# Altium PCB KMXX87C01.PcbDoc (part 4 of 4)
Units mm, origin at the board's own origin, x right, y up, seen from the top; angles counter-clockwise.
Board outline 109.2 x 85.1 mm, 4 copper layers (Top Layer, Mid-Layer 1, Mid-Layer 2, Bottom Layer); 294 components, 222 nets, 951 pads, 352 vias.
Unrouted connection lines stored in the file: 266.
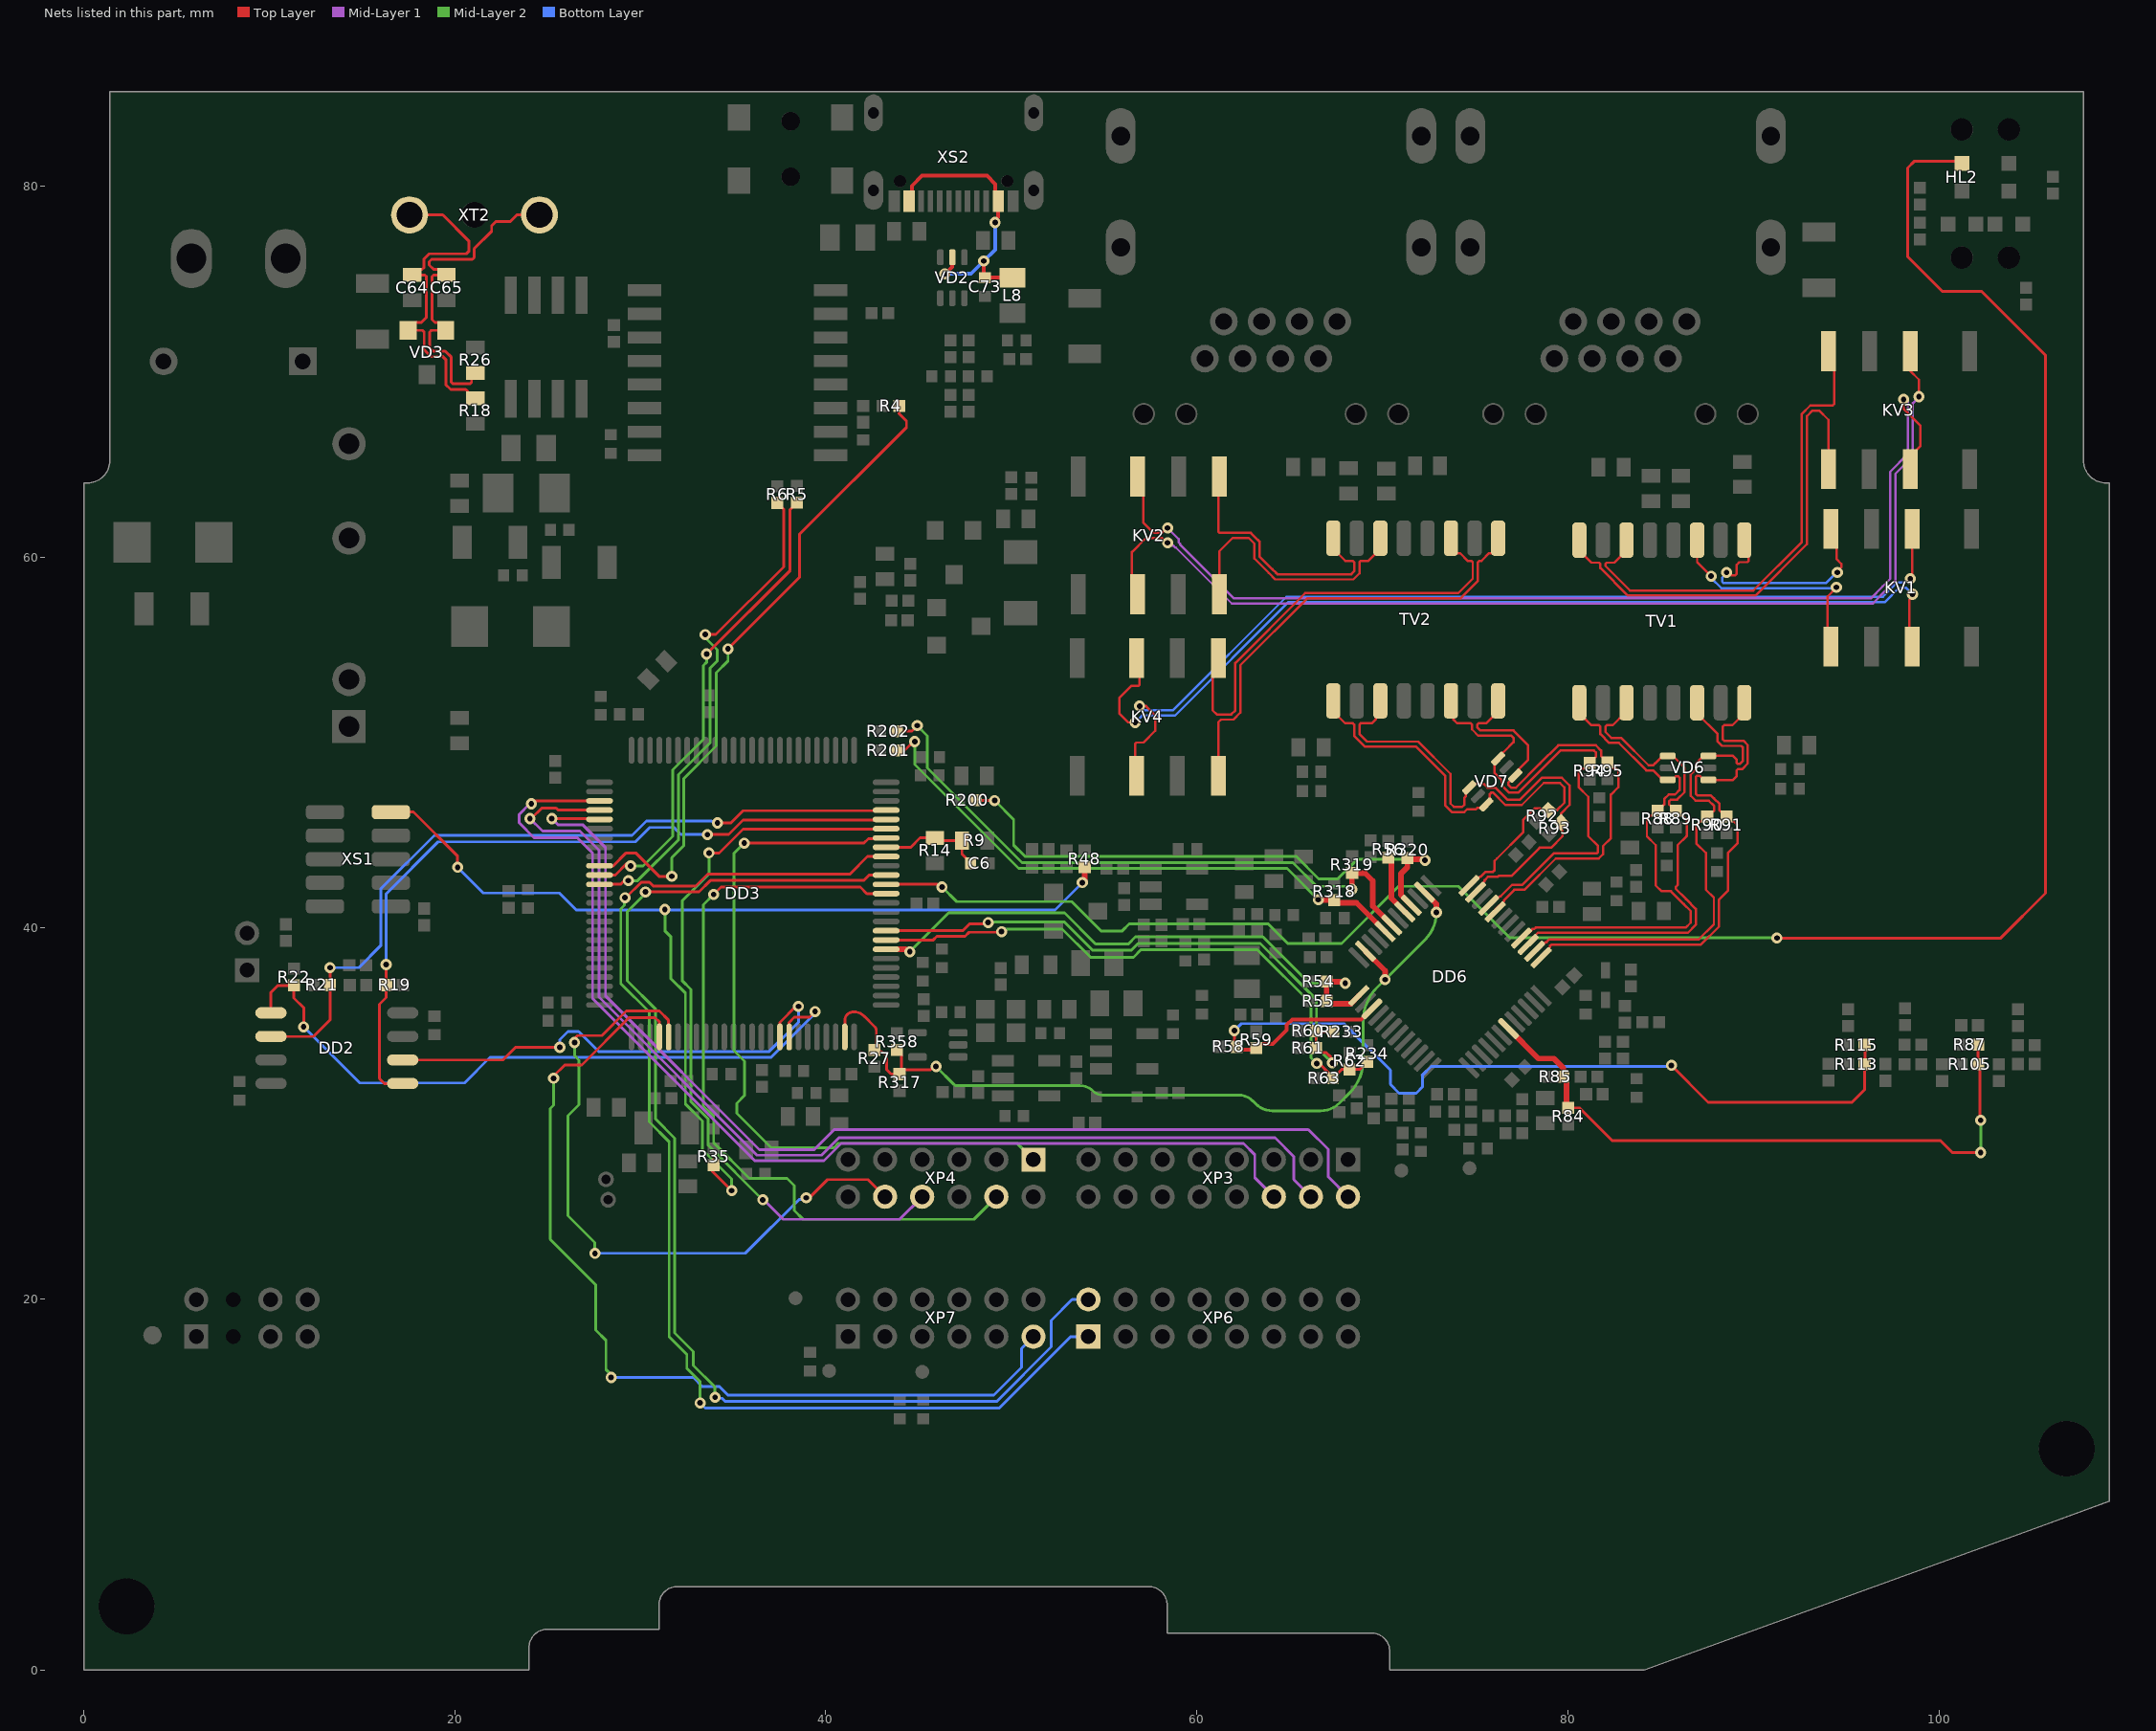
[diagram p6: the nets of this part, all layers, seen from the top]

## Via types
v1: diameter 0.6, hole 0.3, Top Layer to Bottom Layer, tented both sides, 292 vias
v2: diameter 0.6, hole 0.3, Top Layer to Bottom Layer, 60 vias

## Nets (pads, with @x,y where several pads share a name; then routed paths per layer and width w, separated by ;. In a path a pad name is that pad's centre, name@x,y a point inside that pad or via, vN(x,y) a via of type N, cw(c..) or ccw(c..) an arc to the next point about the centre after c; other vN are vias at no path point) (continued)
PE5: DD3.4 XP7.11 | length 50.7
  Top Layer w0.15: v1(25.325,31.9) 25.325,32.018 25.932,32.625 26.841,32.625 29.391,35.175 30.8,35.175 31.025,34.95 DD3.4@31.025,34.132
  Mid-Layer 2 w0.15: v1(25.325,31.9) 25.332,31.893 25.332,30.455 25.15,30.273 25.15,23.219 27.6,20.769 27.6,18.326 28.15,17.776 28.15,16.196 28.277,16.069 28.277,16.047 28.426,15.898 v1(28.426,15.776)
  Bottom Layer w0.15: v1(28.426,15.776) 32.849,15.776 33.35,15.275 34.275,15.275 34.725,14.825 49.06,14.825 50.55,16.315 50.55,17.331 XP7.11@51.195,17.976
PE6: DD3.5 XP4.10 | length 37
  Top Layer w0.15: v1(26.451,33.827) 26.451,34.035 26.5,34.084 26.621,34.204 27.926,34.204 29.246,35.525 31.026,35.525 31.525,35.026 DD3.5@31.525,34.132 ; v1(38.943,25.457) 39.068,25.457 39.087,25.437 40.09,26.44 42.27,26.44 XP4.10@43.195,25.515
  Mid-Layer 2 w0.15: v1(26.451,33.827) 26.451,33.124 26.5,33.075 26.699,32.876 26.699,30.478 26.1,29.879 26.1,24.5 27.55,23.05 27.55,22.467 v1(27.556,22.461)
  Bottom Layer w0.15: v1(27.556,22.461) 27.565,22.47 35.659,22.47 38.564,25.375 38.862,25.375 v1(38.943,25.457)
PE7: DD3.38 XP4.4 | length 41.7
  Top Layer w0.15: v1(33.952,41.811) 34.357,42.215 41.851,42.215 42.209,41.857 DD3.38@43.25,41.857
  Mid-Layer 2 w0.15: v1(33.952,41.811) 33.4,41.258 33.4,30.394 33.952,29.841 33.952,28.423 35.875,26.5 37.913,26.5 38.3,26.113 38.3,24.781 38.78,24.301 47.981,24.301 XP4.4@49.195,25.515
PE9: DD3.40 XP6.2 | length 66.3
  Top Layer w0.15: v1(30.275,41.95) 33.16,41.95 33.775,42.565 42.04,42.565 42.332,42.857 DD3.40@43.25,42.857
  Mid-Layer 2 w0.15: v1(30.275,41.95) 30.275,41.863 29.299,40.887 29.299,37.151 30.827,35.623 30.827,29.696 31.852,28.67 31.852,18.168 32.86,17.16 32.86,16.419 34.027,15.252 v1(34.027,14.7)
  Bottom Layer w0.15: v1(34.027,14.7) 34.073,14.654 34.402,14.654 34.58,14.475 49.205,14.475 52.15,17.42 52.15,18.85 53.276,19.976 XP6.2@54.153,19.976
PE11: DD3.42 XP6.1 | length 66.9
  Top Layer w0.15: v1(29.174,41.64) 29.223,41.64 30.058,42.475 30.492,42.475 30.702,42.265 32.98,42.265 33.63,42.915 41.303,42.915 42.245,43.857 DD3.42@43.25,43.857
  Mid-Layer 2 w0.15: v1(29.174,41.64) 29.174,41.602 29.144,41.572 29.144,41.227 28.949,41.032 28.949,37.006 30.477,35.478 30.477,29.551 31.552,28.475 31.552,17.973 32.51,17.015 32.51,16.26 33.225,15.545 v1(33.225,14.4)
  Bottom Layer w0.15: v1(33.225,14.4) 33.5,14.125 49.35,14.125 53.201,17.976 XP6.1@54.153,17.976
PE13: DD3.44 XP4.1 | length 40.1
  Top Layer w0.15: v1(35.6,44.581) 42.055,44.581 42.292,44.818 42.53,44.818 42.54,44.829 DD3.44@43.209,44.829
  Mid-Layer 2 w0.15: v1(35.6,44.581) 35.05,44.031 35.05,33.39 35.617,32.822 35.617,30.975 35.2,30.558 35.2,30.019 37.061,28.157 40.442,28.157 40.685,28.4 50.311,28.4 XP4.1@51.195,27.515
PE14: DD3.45 XP4.8 | length 40.7
  Top Layer w0.15: v1(33.7,44.05) 34.255,44.05 35.533,45.327 43.22,45.327 DD3.45@43.25,45.357
  Mid-Layer 1 w0.15: v1(36.602,25.351) 36.656,25.351 36.69,25.317 37.706,24.301 43.981,24.301 XP4.8@45.195,25.515
  Mid-Layer 2 w0.15: v1(33.7,44.05) 33.7,42.914 32.254,41.468 32.254,37.166 32.729,36.691 32.729,30.641 33.652,29.717 33.652,28.298 36.6,25.351 v1(36.602,25.351)
PWR_OK: C6.1 DD3.43 R9.1 R14.2 | length 5.8
  Top Layer w0.15: DD3.43@43.25,44.357 44.577,44.357 45.082,44.862 R14.2@45.882,44.862 46.028,44.717 R9.1@47.339,44.717 47.339,43.991 47.806,43.524 C6.1@47.806,43.499
R\E\S\E\T\: R35.2 R48.1 XS1.9 | length 60.1
  Top Layer w0.15: XS1.9@16.55,46.255 17.77,46.255 20.15,43.875 v1(20.15,43.275) ; R35.2@33.95,27.5 33.878,27.428 33.878,26.897 v1(34.925,25.85)
  Top Layer w0.3: v1(53.828,42.452) 53.954,42.579 R48.1@53.954,43.278
  Mid-Layer 2 w0.15: v1(31.325,41.002) 31.325,39.852 31.635,39.542 31.635,37.29 32.429,36.496 32.429,30.517 33.352,29.593 33.352,28.048 34.925,26.475 v1(34.925,25.85)
  Bottom Layer w0.15: v1(20.15,43.275) 21.536,41.889 25.636,41.889 26.55,40.975 31.298,40.975 v1(31.325,41.002) ; v1@31.325,40.975 52.351,40.975 v1(53.828,42.452)
RD1_N: DD6.1 R91.1 TV1.8 VD6.1 | length 28.7
  Top Layer w0.127: DD6.1@78.564,38.404 78.564,38.516 79.044,38.996 79.044,39.041 79.119,39.116 87.178,39.116 88.15,40.087 88.15,41.539 88.624,42.013 88.624,44.046 89.147,44.57 89.147,45.544 88.943,45.748 88.82,45.748 88.297,46.271 88.249,46.271 88.175,46.345 88.175,46.692 87.878,46.989 87.872,46.989 87.714,47.147 87.003,47.147 86.901,47.249 86.901,48.144 86.975,48.219 87.081,48.219 87.102,48.198 87.123,48.198 VD6.1@87.335,47.986 ; VD6.1@87.585,47.986 87.587,47.984 88.899,47.984 89.093,48.178 89.093,48.493 89.167,48.568 89.387,48.568 89.702,48.883 89.702,49.862 89.465,50.099 88.426,50.099 88.352,50.173 88.352,50.862 88.426,50.937 88.867,50.937 89.51,51.58 TV1.8@89.51,52.15
RD1_P: DD6.2 R90.1 TV1.6 VD6.3 | length 28.7
  Top Layer w0.127: DD6.2@78.211,38.757 78.323,38.757 78.803,39.237 78.848,39.237 79.004,39.393 87.064,39.393 87.873,40.202 87.873,41.637 87.447,42.063 87.447,44.046 86.925,44.568 86.925,45.544 87.13,45.748 87.252,45.748 87.775,46.271 87.823,46.271 87.898,46.345 87.898,46.578 87.823,46.652 87.817,46.652 87.599,46.87 86.887,46.87 86.624,47.133 86.624,48.259 86.896,48.531 86.896,48.869 87.202,49.175 87.21,49.175 87.322,49.286 VD6.3@87.585,49.286 88.899,49.286 89.093,49.093 89.093,48.919 89.167,48.845 89.272,48.845 89.425,48.997 89.425,49.747 89.351,49.822 88.312,49.822 88.075,50.058 88.075,50.458 86.97,51.563 TV1.6@86.97,52.15
RD2_N: DD6.8 R95.1 TV2.8 VD7.1 | length 27.6
  Top Layer w0.127: DD6.8@76.089,40.878 76.089,40.991 76.569,41.471 76.569,41.516 77.117,42.063 77.665,42.063 79.351,43.75 81.665,43.75 81.902,43.987 81.902,44.427 82.325,44.85 82.325,47.193 82.727,47.595 82.727,48.463 82.573,48.618 82.45,48.618 R95.1@82.139,48.929 81.877,49.191 81.871,49.191 81.796,49.265 81.796,49.57 81.517,49.849 79.483,49.849 78.494,48.861 77.209,47.576 76.947,47.576 76.789,47.734 76.789,47.839 77.162,48.213 VD7.1@77.162,48.218 77.348,48.404 77.348,48.541 77.395,48.588 77.395,48.602 77.85,49.057 77.85,49.871 77.071,50.65 75.287,50.65 75.112,50.825 75.112,50.962 75.187,51.037 75.6,51.037 76.244,51.68 TV2.8@76.244,52.25
RD2_P: DD6.9 R94.1 TV2.6 VD7.3 | length 27.6
  Top Layer w0.127: TV2.6@73.704,52.25 73.838,52.116 73.838,51.237 74.038,51.037 74.761,51.037 74.835,50.962 74.835,50.71 75.173,50.373 76.956,50.373 77.07,50.259 77.07,50.026 76.884,49.839 76.865,49.822 76.847,49.804 76.243,49.199 VD7.3@76.243,49.137 76.243,49.001 76.051,48.809 76.051,48.356 76.423,47.984 76.423,47.708 76.832,47.299 77.324,47.299 79.598,49.572 81.403,49.572 81.519,49.456 81.519,49.252 R94.1@81.445,49.177 ; DD6.9@75.736,41.232 75.848,41.232 76.328,41.712 76.373,41.712 77.002,42.34 77.55,42.34 79.236,44.027 81.551,44.027 81.625,44.101 81.625,44.425 81.101,44.949 81.101,47.075 80.594,47.582 80.594,48.45 80.749,48.604 80.871,48.604 R94.1@81.183,48.916 R94.1@81.444,49.177
Ref_Clk_Out_Dis: DD6.17 R56.2 | length 3.2
  Top Layer w0.3: R56.2@70.487,43.791 70.487,41.602 DD6.17@71.21,40.878
RMII_CLK: DD3.24 DD6.14 DD6.23 R27.1 R317.2 R358.1 | length 48.1
  Top Layer w0.15: DD3.24@41.025,34.132 41.025,35.037 cw(c41.452,35.037) 41.15,35.338 cw(c41.498,34.991) 41.498,35.483 cw(c41.498,34.666) 42.075,35.243 42.635,34.683 cw(c42.431,34.479) 42.72,34.479 R27.1@42.72,33.562 ; R27.1@42.625,33.425 cw(c42.625,32.613) 43.199,33.187 43.222,33.165 cw(c43.109,33.052) 43.268,33.052 43.268,32.384 43.527,32.125 44.076,32.125 R317.2@44.076,32.352 ; R358.1@43.835,33.428 44.076,33.187 R317.2@44.076,32.352 ; v1(45.938,32.537) 45.851,32.45 45.728,32.45 45.63,32.352 R317.2@44.076,32.352
  Top Layer w0.3: DD6.23@69.089,38.757 70.15,37.696 v2(70.149,37.223) ; DD6.14@72.271,41.939 72.912,41.298 v1(72.912,40.848)
  Mid-Layer 2 w0.15: v1(45.938,32.537) 46.904,31.572 ccw(c47.063,31.731) 47.063,31.506 53.686,31.506 cw(c53.686,30.461) 54.425,31.2 ccw(c54.914,31.689) 54.914,30.997 62.25,30.997 cw(c62.25,29.904) 63.023,30.677 63.179,30.521 ccw(c64.075,31.417) 64.075,30.15 66.674,30.15 ccw(c66.674,31.601) 67.7,30.575 68.231,31.106 ccw(c66.435,32.902) 68.975,32.902 68.975,34.997 cw(c71.515,34.997) 69.719,36.793 v2(70.149,37.223) 72.303,39.376 ccw(c70.831,40.848) v1(72.912,40.848)
RMII_CRS_DV: DD3.32 DD6.25 R54.1 R55.1 | length 31.6
  Top Layer w0.3: DD3.32@43.25,38.857 44.313,38.857 44.445,38.726 v1(44.526,38.726) ; R55.1@66.996,36.073 R55.1@66.996,36.088 ; v1(68,37.025) 67.917,37.108 66.999,37.108 R54.1@66.996,37.112 R55.1@66.996,36.088 ; DD6.25@68.736,36.353 68.295,35.913 67.171,35.913 R55.1@66.996,36.088
  Mid-Layer 2 w0.15: v1(44.526,38.726) 46.614,40.814 47.528,40.814 47.539,40.825 52.865,40.825 54.54,39.15 56.315,39.15 56.69,39.525 63.56,39.525 66.06,37.025 v1(68,37.025)
RMII_RXD0: DD3.33 R62.1 R63.1 R234.2 | length 32
  Top Layer w0.15: DD3.33@43.25,39.357 45.789,39.357 45.982,39.55 47.501,39.55 47.726,39.775 49.442,39.775 v1(49.475,39.808) ; v1(66.463,32.7) 66.549,32.614 66.679,32.614 67.075,32.218 67.075,32.15 R63.1@67.325,31.9 67.802,32.377 R62.1@68.237,32.377 68.776,32.377 R234.2@69.183,32.784
  Mid-Layer 2 w0.15: v1(49.475,39.808) 49.617,39.95 52.75,39.95 54.275,38.425 56.58,38.425 56.98,38.825 63.27,38.825 66.153,35.942 66.153,33.01 v1(66.463,32.7)
RMII_RXD1: DD3.34 R60.1 R61.1 R233.2 | length 32
  Top Layer w0.15: DD3.34@43.25,39.857 43.257,39.864 47.391,39.864 47.752,40.225 48.675,40.225 v1(48.75,40.3) ; R61.1@66.425,33.496 66.425,34.404 R233.2@67.35,34.404 ; R61.1@66.425,33.525 66.672,33.278 66.985,33.278 67.222,33.041
  Mid-Layer 2 w0.15: v1(48.75,40.3) 48.783,40.333 52.862,40.333 54.395,38.8 56.46,38.8 56.835,39.175 63.415,39.175 66.453,36.137 66.453,33.583 v1(67.308,32.728)
RMII_TX_EN: DD6.16 R200.2 R320.1 | length 31.1
  Top Layer w0.15: R200.2@48.083,46.892 48.117,46.857 48.137,46.877 v1(49.102,46.877)
  Top Layer w0.3: R320.1@71.356,43.771 71.356,43.284 70.998,42.925 70.998,41.798 71.175,41.621 DD6.16@71.564,41.232 ; R320.1@71.437,43.708 72.248,43.708 v1(72.3,43.656)
  Mid-Layer 2 w0.15: v1(49.102,46.877) 50.124,45.855 50.124,44.474 50.727,43.871 65.354,43.871 66.575,42.65 67.592,42.65 68.642,43.7 72.256,43.7 v1(72.3,43.656)
RMII_TXD0: DD6.20 R201.2 R318.1 | length 31.5
  Top Layer w0.15: R201.2@43.82,49.582 44.26,49.582 44.731,50.054 v1(44.793,50.054)
  Top Layer w0.3: v1(66.548,41.527) 66.559,41.516 67.404,41.516 R318.1@67.415,41.505 67.562,41.357 68.61,41.357 69.761,40.207 DD6.20@70.15,39.818
  Mid-Layer 2 w0.15: v1(44.793,50.054) 44.793,48.816 50.394,43.214 64.861,43.214 v1(66.548,41.527)
RMII_TXD1: DD6.19 R202.2 R319.1 | length 34.3
  Top Layer w0.15: R202.2@43.829,50.6 43.858,50.629 44.641,50.629 v1(44.927,50.915)
  Top Layer w0.3: v1(68.357,42.083) 68.357,42.95 R319.1@68.372,42.966 69.068,42.966 69.487,42.547 69.487,41.188 DD6.19@70.503,40.171
  Mid-Layer 2 w0.15: v1(44.927,50.915) 45.475,50.367 45.475,48.628 50.582,43.521 65.179,43.521 66.45,42.25 68.068,42.25 68.235,42.083 v1(68.357,42.083)
RS485_N: C64.2 R18.1 VD3.2 XT2.3 | length 18.9
  Top Layer w0.15: XT2.3@17.56,78.451 19.349,78.451 20.75,77.05 20.75,76.477 20.622,76.348 18.623,76.348 18.324,76.049 18.324,75.595 18.236,75.507 18.123,75.507 C64.2@17.823,75.207 ; C64.2@17.698,75.207 C64.2@17.823,75.207 ; R18.1@21.1,68.566 20.975,68.566 20.675,68.866 20.675,68.951 20.587,69.039 19.776,69.039 19.512,69.302 19.512,70.65 19.354,70.809 18.714,70.809 18.348,71.175 18.348,72.133 18.26,72.221 VD3.2@17.482,72.221 17.482,72.272 17.864,72.654 18.197,72.654 18.473,72.93 18.473,75.12 18.385,75.207 C64.2@17.823,75.207
RS485_P: C65.2 R26.1 VD3.1 XT2.1 | length 18.9
  Top Layer w0.15: C65.2@19.548,75.207 C65.2@19.218,75.207 ; R26.1@21.106,69.939 20.9,69.733 20.9,69.426 20.812,69.339 19.9,69.339 19.812,69.426 19.812,70.774 19.478,71.109 18.838,71.109 18.648,71.299 18.648,72.133 18.736,72.221 VD3.1@19.514,72.221 19.514,72.272 19.132,72.654 18.921,72.654 18.773,72.802 18.773,75.12 18.861,75.207 C65.2@19.218,75.207 ; XT2.1@24.56,78.451 23.35,78.451 22.999,78.1 22.225,78.1 21.984,77.859 21.984,77.565 21.05,76.631 21.05,76.149 20.949,76.048 18.747,76.048 18.624,75.925 18.624,75.744 18.861,75.507 19.123,75.507 19.218,75.413 C65.2@19.218,75.207
RS485_RTS: DD3.85 R4.1 | length 35.5
  Top Layer w0.15: DD3.85@27.8,43.357 28.542,43.357 29.237,44.052 29.748,44.052 31.01,42.79 v1(31.695,42.79) ; v1(34.727,55.053) 38.574,58.9 38.574,61.218 44.345,66.989 44.345,67.341 43.95,67.737 R4.1@43.95,68.156
  Mid-Layer 2 w0.15: v1(31.695,42.79) 31.695,43.795 32.35,44.45 32.35,48.075 34.1,49.825 34.1,53.775 34.727,54.402 v1(34.727,55.053)
RS485_RX: DD3.87 R6.1 | length 26.8
  Top Layer w0.15: DD3.87@27.8,42.357 28.929,42.357 29.177,42.606 29.227,42.556 v1(29.352,42.556) ; v1(33.5,55.825) 34.075,55.825 37.725,59.475 37.725,62.575 R6.1@37.375,62.925
  Mid-Layer 2 w0.15: v1(29.352,42.556) 29.851,42.556 32.05,44.755 32.05,48.275 33.75,49.975 33.75,54.005 34.145,54.4 34.145,55.013 33.5,55.658 v1(33.5,55.825)
RS485_TX: DD3.86 R5.1 | length 25.7
  Top Layer w0.15: DD3.86@27.8,42.857 28.65,42.857 29.263,43.47 29.386,43.347 v1(29.475,43.347) ; v1(33.57,54.775) 38.075,59.28 38.075,62.569 R5.1@38.441,62.935
  Mid-Layer 2 w0.15: v1(29.475,43.347) 30.147,43.347 31.75,44.95 31.75,48.525 33.4,50.175 33.4,54.15 33.57,54.32 v1(33.57,54.775)
RX_N: KV1.2 KV4.2 | length 52.8
  Top Layer w0.127: KV4.2@56.757,48.204 56.675,48.286 56.675,49.929 56.749,50.003 57.124,50.003 57.758,50.638 57.758,51.473 57.262,51.969 v2(56.913,51.969) ; v2(98.46,58.836) 98.412,58.836 98.329,58.753 98.575,58.753 KV1.2@98.575,61.524
  Bottom Layer w0.127: v2(56.913,51.969) 56.955,51.969 57.191,51.732 58.701,51.732 64.826,57.857 96.985,57.857 97.759,58.631 98.151,58.631 98.356,58.836 v2(98.46,58.836)
RX_P: KV1.7 KV4.7 | length 52.8
  Top Layer w0.127: v2(56.675,51.087) 56.303,51.087 55.83,51.559 55.83,52.417 56.465,53.052 56.839,53.052 56.913,53.126 56.913,54.398 KV4.7@56.757,54.554 ; KV1.7@98.575,55.174 98.4,55.349 98.4,57.697 98.575,57.872 v2(98.575,58)
  Bottom Layer w0.127: v2(56.675,51.087) 57.044,51.455 58.816,51.455 64.941,57.58 97.099,57.58 97.869,58.35 98.225,58.35 v2(98.575,58)
Speed_Conf_P1: DD6.43 R84.2 R85.1 R87.1 R105.1 | length 35.1
  Top Layer w0.15: R84.2@80.025,30.308 80.623,30.308 82.38,28.55 100.078,28.55 100.728,27.9 v1@102.225,27.9 ; R87.1@102.112,33.711 R105.1@102.112,32.661 102.225,32.547 v1@102.225,29.643
  Top Layer w0.3: DD6.43@76.797,34.585 78.413,32.968 79.247,32.968 79.764,32.452 R85.1@79.764,31.982 79.935,31.812 79.935,30.44 R84.2@80.025,30.35
  Mid-Layer 2 w0.15: v1(102.258,27.9) v1(102.258,29.643)
Speed_Conf_P2: DD6.27 R58.2 R59.1 R113.1 R115.1 | length 50.2
  Top Layer w0.15: v1(62.025,34.475) 62.025,33.621 62.153,33.493 62.153,33.597 R58.2@62.15,33.6 ; v1(85.582,32.599) 87.572,30.61 95.317,30.61 95.997,31.291 R113.1@95.997,32.656 ; R113.1@96.022,32.656 R115.1@96.022,33.675
  Top Layer w0.2: R58.2@62.153,33.493 62.195,33.451 63.2,33.451 63.2,33.521 63.425,33.746 64.09,33.746 64.842,34.497 64.842,34.776 65.14,35.075 68.872,35.075 DD6.27@69.443,35.646
  Bottom Layer w0.15: v1(62.025,34.475) 62.4,34.85 67.925,34.85 70.431,32.344 70.431,31.576 70.907,31.1 71.825,31.1 72.175,31.45 72.175,32.087 72.625,32.538 85.521,32.538 v1(85.582,32.599)
SPI2_CS: DD2.1 DD3.46 R19.1 | length 40.4
  Top Layer w0.15: v1(16.296,38.032) 16.296,36.929 R19.1@16.3,36.925 16.3,36.25 15.94,35.89 15.94,31.885 16.206,31.619 DD2.1@17.19,31.619 ; v1(33.615,45.041) 33.623,45.05 34.76,45.05 35.538,45.828 42.539,45.828 42.54,45.829 43.221,45.829 DD3.46@43.25,45.857
  Bottom Layer w0.15: v1(16.296,38.032) 16.296,38.05 16.305,38.059 16.305,41.855 19.1,44.65 29.732,44.65 30.504,45.422 31.808,45.422 32.189,45.041 v1(33.615,45.041)
SPI2_MISO: DD2.2 DD3.17 | length 26.3
  Top Layer w0.15: DD2.2@17.19,32.889 22.589,32.889 23.275,33.575 v1(25.661,33.575) ; DD3.17@37.525,34.132 37.525,34.915 38.393,35.783 38.401,35.775 v1(38.525,35.775)
  Bottom Layer w0.15: v1(25.661,33.575) 25.661,33.986 26.1,34.425 26.674,34.425 27.749,33.35 36.949,33.35 38.525,34.926 v1(38.525,35.775)
SPI2_MOSI: DD2.5 DD3.18 R22.1 | length 37.9
  Top Layer w0.15: DD2.5@10.09,35.429 10.09,36.537 10.46,36.907 R22.1@11.325,36.907 11.325,36.232 11.85,35.707 v1(11.85,34.675) ; DD3.18@38.025,34.132 38.025,34.92 38.305,35.2 39.123,35.2 v1(39.425,35.502)
  Bottom Layer w0.15: v1(11.85,34.675) 14.875,31.65 20.525,31.65 21.9,33.025 37.048,33.025 39.425,35.402 v1(39.425,35.502)
SPI2_SCK: DD2.6 DD3.47 R21.1 | length 42.2
  Top Layer w0.15: DD2.6@10.09,34.159 10.098,34.15 12.375,34.15 13.275,35.05 R21.1@13.275,36.925 v1(13.275,37.865) ; v1(34.157,45.667) 34.882,45.667 35.544,46.329 DD3.47@43.673,46.329
  Bottom Layer w0.15: v1(13.275,37.865) 14.821,37.865 16.005,39.049 16.005,42.105 18.9,45 29.55,45 30.322,45.772 33.845,45.772 33.863,45.753 34.071,45.753 v1(34.157,45.667)
SPI3_MISO: DD3.79 XP3.4 | length 60.7
  Top Layer w0.15: v1(24.05,45.9) 24.115,45.9 24.69,46.475 25.463,46.475 25.563,46.375 27.782,46.375 DD3.79@27.8,46.357
  Mid-Layer 1 w0.15: v1(24.05,45.9) 24.725,45.225 26.745,45.225 27.775,44.195 27.775,36.274 36.292,27.757 39.775,27.757 40.708,28.691 64.215,28.691 65.225,27.681 65.225,26.444 XP3.4@66.153,25.515
SPI3_MOSI: DD3.80 XP3.2 | length 60.4
  Top Layer w0.15: v1(25.225,45.9) 27.757,45.9 DD3.80@27.782,45.875
  Mid-Layer 1 w0.15: v1(25.225,45.9) 25.55,45.575 26.89,45.575 28.125,44.34 28.125,36.349 36.416,28.057 39.367,28.057 40.45,29.141 60.937,29.141 61.413,29.14 66.01,29.141 67.078,28.073 67.078,26.591 XP3.2@68.153,25.515
SPI3_SCK: DD3.78 XP3.6 | length 60.2
  Top Layer w0.15: v1(24.125,46.7) 24.282,46.857 DD3.78@27.8,46.857
  Mid-Layer 1 w0.15: v1(24.125,46.7) 24.037,46.7 23.475,46.138 23.475,45.662 24.262,44.875 26.6,44.875 27.425,44.05 27.425,36.2 36.168,27.457 39.899,27.457 40.833,28.391 62.515,28.391 63.125,27.781 63.125,26.544 XP3.6@64.153,25.515
"System Fault": DD3.39 HL2.A | length 114.1
  Top Layer w0.15: DD3.39@43.25,42.357 45.999,42.357 46.141,42.215 v1(46.263,42.215) ; v1(91.271,39.463) 103.341,39.463 105.75,41.872 105.75,70.883 102.318,74.315 100.202,74.315 98.324,76.193 98.324,80.981 98.693,81.35 101.115,81.35 HL2.A@101.239,81.226
  Mid-Layer 2 w0.15: v1(46.263,42.215) 47.053,41.425 53.255,41.425 54.83,39.85 55.979,39.85 56.354,40.225 63.85,40.225 64.9,39.175 67.8,39.175 70.875,42.25 74.1,42.25 76.875,39.475 91.225,39.475 v1@91.25,39.45
TD1_N: DD6.3 R89.1 TV1.3 VD6.4 | length 27
  Top Layer w0.127: DD6.3@77.972,39.338 78.384,39.75 79.412,39.75 80.215,39.75 86.473,39.75 86.901,40.178 86.901,41.035 86.372,41.564 85.821,42.115 85.821,42.22 85.919,42.319 85.919,44.47 86.399,44.95 86.408,44.958 86.408,45.862 86.204,46.067 86.081,46.067 R89.1@85.82,46.328 85.558,46.59 85.548,46.59 85.474,46.664 85.474,46.844 85.556,46.926 85.893,46.926 86.297,47.33 86.297,48.645 85.753,49.19 VD6.4@85.481,49.19 ; TV1.3@83.16,52.15 83.16,51.649 82.809,51.298 82.779,51.298 82.418,50.937 82.103,50.937 82.029,50.862 82.029,50.574 82.344,50.259 82.866,50.259 84.35,48.775 84.602,48.775 84.696,48.869 85.002,49.175 85.01,49.175 85.122,49.286 VD6.4@85.385,49.286
TD1_P: DD6.4 R88.1 TV1.1 VD6.6 | length 27
  Top Layer w0.127: DD6.4@77.504,39.464 77.616,39.464 78.096,39.944 78.187,39.944 78.269,40.027 79.298,40.027 80.215,40.027 86.358,40.027 86.624,40.292 86.624,40.92 86.257,41.287 85.56,41.984 85.054,41.984 84.742,42.296 84.742,44.47 84.262,44.95 ; TV1.1@80.62,52.15 80.62,51.58 81.264,50.937 81.677,50.937 81.752,50.862 81.752,50.46 82.229,49.982 82.751,49.982 84.236,48.498 84.602,48.498 84.902,48.198 85.002,48.098 85.01,48.098 85.122,47.986 VD6.6@85.385,47.986 ; 84.262,45.025 84.262,45.864 84.467,46.068 84.589,46.068 R88.1@84.851,46.33 85.112,46.591 85.123,46.591 85.197,46.666 85.197,46.958 85.442,47.203 85.778,47.203 86.02,47.445 86.02,48.105 85.946,48.179 85.82,48.179 VD6.6@85.627,47.986
TD2_N: DD6.11 R93.1 TV2.3 VD7.4 | length 27.4
  Top Layer w0.127: TV2.3@69.894,52.25 69.655,52.012 69.655,51.268 69.424,51.037 68.837,51.037 68.762,50.962 68.762,50.475 69.183,50.054 71.938,50.054 73.677,48.315 73.677,46.715 73.86,46.531 74.306,46.531 74.412,46.637 74.412,47.007 74.511,47.106 74.511,47.405 VD7.4@74.688,47.582 74.874,47.768 75.031,47.768 75.037,47.774 75.469,47.774 75.484,47.759 75.668,47.575 76.093,47.575 76.752,46.916 77.404,46.916 78.59,48.102 79.684,48.102 80.09,47.697 80.09,46.637 79.622,46.169 79.622,46.064 79.623,46.062 R93.1@79.623,45.693 79.623,45.323 79.71,45.236 79.71,44.947 79.096,44.333 78.483,44.333 76.962,42.812 76.271,42.812 76.216,42.756 75.688,42.756 75.509,42.577 75.509,42.531 75.029,42.051 75.029,42 DD6.11@75.029,41.939
TD2_P: DD6.12 R92.1 TV2.1 VD7.6 | length 26.4
  Top Layer w0.127: TV2.1@67.354,52.25 67.354,51.68 67.997,51.037 68.411,51.037 68.485,50.962 68.485,50.36 69.069,49.777 71.823,49.777 73.4,48.2 73.4,46.6 73.746,46.254 74.421,46.254 74.571,46.404 75.049,46.404 75.131,46.486 VD7.6@75.43,46.486 ; DD6.12@74.675,42.293 74.787,42.293 75.267,42.773 75.313,42.773 75.574,43.033 75.963,43.033 76.038,43.108 76.038,43.608 76.176,43.747 76.176,43.75 77.587,45.161 77.587,45.833 78.201,46.447 78.49,46.447 78.577,46.36 R92.1@78.947,46.36 79.421,46.36 79.813,46.752 79.813,47.582 79.569,47.825 78.705,47.825 77.519,46.639 76.638,46.639 75.978,47.298 75.873,47.298 75.793,47.218 75.793,46.849 VD7.6@75.607,46.663
TV1_RX_N: KV1.4 TV1.9 | length 12.8
  Top Layer w0.127: v2(88.559,59.175) 88.687,59.175 88.837,59.025 89.026,59.025 89.1,59.099 89.1,59.58 89.247,59.727 89.676,59.727 89.75,59.802 89.75,59.954 89.749,59.956 89.749,60.677 TV1.9@89.51,60.915 ; KV1.4@94.175,61.524 94.48,61.219 94.48,59.9 94.75,59.63 94.75,59.465 94.532,59.247 v2(94.532,59.169)
  Bottom Layer w0.127: v2(88.559,59.175) 88.559,59.13 88.324,58.895 88.324,58.674 88.399,58.6 93.913,58.6 94.482,59.169 v2(94.532,59.169)
TV1_RX_P: KV1.5 TV1.11 | length 12.8
  Top Layer w0.127: TV1.11@86.97,60.915 86.97,59.73 v2@87.725,58.975 ; KV1.5@94.175,55.174 94,55.349 94,57.873 94.48,58.353 v2(94.48,58.371)
  Bottom Layer w0.127: v2(87.725,58.975) 87.725,58.882 88.284,58.323 94.432,58.323 v2(94.48,58.371)
TV1_TX_N: KV3.4 TV1.14 | length 26.2
  Top Layer w0.127: TV1.14@83.16,60.915 83.16,60.345 82.517,59.702 82.103,59.702 82.029,59.627 82.029,59.522 83.349,58.202 89.999,58.202 92.614,60.817 92.614,67.717 93.072,68.175 94.276,68.175 94.35,68.249 94.35,70.8 KV3.4@94.05,71.1
TV1_TX_P: KV3.5 TV1.16 | length 26.2
  Top Layer w0.127: TV1.16@80.62,60.915 80.62,60.345 81.264,59.702 81.677,59.702 81.752,59.627 81.752,59.407 83.234,57.925 90.114,57.925 92.891,60.702 92.891,67.602 93.186,67.898 93.552,67.898 94.05,67.4 KV3.5@94.05,64.75
TV2_RX_N: KV4.4 TV2.9 | length 24.5
  Top Layer w0.127: KV4.4@61.157,48.204 61.157,51.098 61.3,51.24 61.972,51.24 62.352,51.62 62.352,54.177 65.95,57.775 74.204,57.775 75.151,58.721 75.151,59.727 75.225,59.802 75.352,59.802 75.757,60.207 75.937,60.207 76.244,60.514 TV2.9@76.244,61.015
TV2_RX_P: KV4.5 TV2.11 | length 24.5
  Top Layer w0.127: KV4.5@61.157,54.554 60.85,54.246 60.85,51.745 61.078,51.517 61.857,51.517 62.075,51.735 62.075,54.292 65.835,58.052 74.089,58.052 74.874,58.836 74.874,59.727 74.799,59.802 74.596,59.802 74.191,60.207 74.011,60.207 73.704,60.514 TV2.11@73.704,61.015
TV2_TX_N: KV2.4 TV2.14 | length 14.3
  Top Layer w0.127: KV2.4@61.217,57.995 61.217,60.317 61.932,61.032 62.793,61.032 63.1,60.725 63.1,59.925 63.875,59.15 64.227,58.798 68.438,58.798 68.762,59.122 68.762,59.727 68.837,59.802 69.25,59.802 69.894,60.445 TV2.14@69.894,61.015
TV2_TX_P: KV2.5 TV2.16 | length 14.3
  Top Layer w0.127: KV2.5@61.217,64.345 61.157,64.285 61.157,61.383 61.232,61.309 62.908,61.309 63.296,60.921 63.377,60.84 63.377,60.04 64.071,59.346 64.267,59.15 64.342,59.075 68.323,59.075 68.485,59.237 68.485,59.727 68.411,59.802 67.997,59.802 67.354,60.445 TV2.16@67.354,61.015
TX_N: KV2.2 KV3.2 | length 59.4
  Top Layer w0.127: KV2.2@56.817,57.995 56.5,58.313 56.5,60.275 57.257,61.032 57.734,61.032 58.114,61.032 58.376,60.77 v2(58.425,60.77) ; KV3.2@98.45,71.1 98.163,70.813 98.693,70.284 98.45,70.04 98.925,69.565 v2(98.925,68.65)
  Mid-Layer 1 w0.127: v2(58.425,60.77) 58.553,60.77 58.696,60.627 58.721,60.627 58.834,60.514 58.871,60.514 61.887,57.498 96.44,57.498 97.269,58.327 97.654,58.712 97.654,64.486 98.601,65.434 98.601,68.297 98.925,68.621 v2(98.925,68.65)
TX_P: KV2.7 KV3.7 | length 59.7
  Top Layer w0.127: KV2.7@56.817,64.345 57.124,64.039 57.124,61.847 57.662,61.309 58.114,61.309 58.376,61.57 v2(58.425,61.57) ; v2(98.105,68.503) 98.105,67.99 99.013,67.081 99.013,65.988 98.45,65.425 KV3.7@98.45,64.75
  Mid-Layer 1 w0.127: v2(58.425,61.57) 59.017,60.978 59.017,60.797 59.092,60.722 59.092,60.685 62.002,57.775 96.325,57.775 96.975,58.425 97.377,58.827 97.377,64.601 98.324,65.548 v2@98.324,68.412
Vbus: C73.2 L8.1 VD2.5 XS2.A4_B9 XS2.B4_A9 | length 16.2
  Top Layer w0.2: XS2.B4_A9@44.49,79.195 44.64,79.345 44.64,80.013 45.19,80.563 48.69,80.563 49.14,80.113 49.14,79.345 XS2.A4_B9@49.29,79.195 49.29,78.313 49.128,78.151 v1(49.128,78.043) ; v1(46.416,75.264) 46.43,75.279 46.46,75.279 46.819,75.638 VD2.5@46.819,76.163 ; v1(48.515,75.966) 48.515,75.129 C73.2@48.58,75.064 50.063,75.064 L8.1@50.069,75.058
  Bottom Layer w0.2: v1(46.416,75.264) 46.43,75.279 47.828,75.279 v1(48.515,75.966) 49.128,76.579 v1(49.128,78.043)
pads on no net: DD3.13 DD3.99 DD4.1 DD6.13 DD6.15 DD9.6 DD9.11 LED-pipe_.MH MH1.1 MH2.1 SB1.MH TV1.4 TV1.5 TV1.12 TV1.13 TV2.4 TV2.5 TV2.12 TV2.13 VD2.1 VD2.3 VD6.5 VD7.5 XP5.3 XP5.4 XS1.7 XS2.A8 XS2.B8 XS2.MH1 XS2.MH2

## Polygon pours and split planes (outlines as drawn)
GND on Mid-Layer 1 "NONET_L-01_P-001" (hatched Horizontal grid 0.2 track 0.2, remove dead copper, pour order 2): 11.455,5.8 1.875,15.38 1.875,46.925 10.13,55.18 14.68,55.18 18.165,51.695 25.72,51.695 35.32,61.295 35.32,76.26 38.46,79.4 49.682,79.4 51.68,77.402 51.68,66.62 53.238,65.062 53.238,45.86 54.622,44.475 62.299,44.475 65.24,47.417 65.24,50.535 66.013,51.308 99.743,51.308 101.41,52.975 101.41,72.865 97.925,76.35 97.925,82.612 99.613,84.3 105.125,84.3 107.2,82.225 107.2,21.85 91.15,5.8
GND_RS on Mid-Layer 1 "NONET_L-01_P-001" (hatched Horizontal grid 0.2 track 0.2, remove dead copper, pour order 0): 12.95,60.605 12.95,62.702 15.5,65.252 15.5,73.254 16.788,74.542 28.9,74.542 30.234,73.209 30.234,61.6 24.458,55.825 19.601,55.825 18.628,56.798 18.628,58.548 18.275,58.9 14.655,58.9
GND on Top Layer "NONET_L-01_P-001" (hatched Horizontal grid 0.2 track 0.2, remove dead copper, pour order 4): 11.455,5.8 1.875,15.38 1.875,46.925 10.13,55.18 14.68,55.18 18.165,51.695 25.72,51.695 35.32,61.295 35.32,76.26 38.46,79.4 49.682,79.4 51.546,77.536 51.546,66.753 53.683,64.616 53.683,45.167 54.8,44.05 61.873,44.05 65.24,47.417 65.24,50.535 66.013,51.308 100.108,51.308 101.41,52.61 101.41,72.865 97.925,76.35 97.925,82.612 99.613,84.3 105.125,84.3 107.2,82.225 107.2,21.85 91.15,5.8
GND_RS on Top Layer "NONET_L-01_P-001" (hatched Horizontal grid 0.2 track 0.2, remove dead copper, pour order 1): 12.95,60.605 12.95,62.702 15.5,65.252 15.5,73.254 16.788,74.542 28.9,74.542 30.234,73.209 30.234,61.6 24.458,55.825 19.601,55.825 18.628,56.798 18.628,58.548 18.275,58.9 14.655,58.9
GND on Mid-Layer 2 "NONET_L-01_P-001" (hatched Horizontal grid 0.2 track 0.2, remove dead copper, pour order 3): 11.455,5.8 1.875,15.38 1.875,46.925 10.13,55.18 14.68,55.18 18.165,51.695 25.72,51.695 35.32,61.295 35.32,76.26 38.46,79.4 49.682,79.4 51.538,77.512 51.538,66.763 53.529,64.771 53.529,45.174 54.228,44.475 62.299,44.475 65.24,47.417 65.24,50.535 66.013,51.308 99.978,51.308 101.41,52.74 101.41,72.865 97.925,76.35 97.925,82.612 99.613,84.3 105.125,84.3 107.2,82.225 107.2,21.85 91.15,5.8
GND on Bottom Layer "NONET_L-01_P-001" (hatched Horizontal grid 0.2 track 0.2, remove dead copper, pour order 5): 11.455,5.8 5.475,11.78 5.475,48.35 12.305,55.18 14.68,55.18 18.165,51.695 25.72,51.695 35.32,61.295 35.32,76.26 38.46,79.4 49.682,79.4 51.538,77.512 51.538,66.763 53.529,64.771 53.529,45.174 54.228,44.475 62.299,44.475 65.24,47.417 65.24,50.535 66.013,51.308 99.978,51.308 101.41,52.74 101.41,72.865 97.925,76.35 97.925,82.612 99.613,84.3 105.125,84.3 107.2,82.225 107.2,21.85 91.15,5.8

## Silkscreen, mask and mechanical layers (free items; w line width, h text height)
Top Overlay:
  lines w0.2: 0.088,21.896 109.2,21.896 ; 0.088,23.55 109.2,23.55
Mechanical 1:
  lines w0.02: 20.04,4.018 20.04,24.018
  lines w2: 11.8,60.875 11.8,66.375 13.6,68.175 13.6,78.775 16.1,81.275 26.4,81.275 29.55,81.275 ; 54.87,45.981 61.874,45.981 62.63,46.737 ; 55.072,46.049 55.072,55.754 ; 99.875,60.963 99.875,70.668
  lines w2.5: 62.85,48.225 63.8,49.175 63.8,53.275 66.275,55.75 92.025,55.75 92.484,55.291 92.484,52.798 92.486,52.8 99.056,52.8
Mechanical 3:
  circle w0.006: c109.2,9 r0.003
Board Outline:
  lines w0.2: 4.015,23.626 ccw(c4.015,22.826) 3.215,22.826 3.215,22.626 ccw(c4.015,22.626) 4.015,21.826 14.105,21.826 ccw(c14.105,22.626) 14.905,22.626 14.905,22.826 ccw(c14.105,22.826) 14.105,23.626 ; 4.015,23.626 4.015,23.626 ; 4.015,23.626 14.105,23.626 ; 14.105,23.626 14.105,23.626 ; 39.15,23.626 ccw(c39.15,22.826) 38.35,22.826 38.35,22.626 ccw(c39.15,22.626) 39.15,21.826 70.198,21.826 ccw(c70.198,22.626) 70.998,22.626 70.998,22.826 ccw(c70.198,22.826) 70.198,23.626 ; 39.15,23.626 70.198,23.626 ; 39.15,23.626 39.15,23.626 ; 70.198,23.626 70.198,23.626 ; 0,0 4,0 24,0 24,1.2 cw(c25,1.2) 25,2.2 31,2.2 31,3.5 cw(c32,3.5) 32,4.5 57.4,4.5 cw(c57.4,3.5) 58.4,3.5 58.4,2 69.4,2 cw(c69.4,1) 70.4,1 70.4,0 84.124,0 105.476,7.748 109.2,9.1 109.2,54.5 109.2,60.2 109.2,64 109,64 cw(c109,65.2) 107.8,65.2 107.8,85.1 106.05,85.1 3.15,85.1 1.4,85.1 1.4,65.2 cw(c0.2,65.2) 0.2,64 0,64 0,60.2 0,54.5 0,0
Testpoint bottom:
  circle w0.013: c2.3,3.5 r1.5
  lines w0.01: 3.15,85.5 106.05,85.5 ; 3.15,86.7 106.05,86.7
  lines w0.013: -0.2,3.5 2.3,3.5 ; 0,54.5 2,54.5 2,9.3 4,9.3 4,0 ; 0,60.2 3.15,60.2 3.15,85.1 ; 2.3,1 2.3,3.5 ; 2.3,6 2.3,3.5 ; 4.8,3.5 2.3,3.5 ; 104.4,12.1 106.9,12.1 ; 105.476,7.648 105.2,7.648 105.2,18 107.2,18 107.2,54.5 109.2,54.5 ; 106.05,85.1 106.05,60.2 109.2,60.2 ; 106.9,9.6 106.9,12.1 ; 106.9,14.6 106.9,12.1 ; 109.4,12.1 106.9,12.1
  text "Все по максимуму ставится на Top слое / (в подвале нет вентиляции)" at -41.004,105.247 h3
  text "Расположение - переключатель, Eth1, Eth2, USB, кнопка, SD" at -37.5,100 h2
  text "Case" at 4.084,85.85 h0.5
  text "Case" at 103.784,85.811 h0.5
  text "Keepout" at 2.687,68.006 h1.2 r90
  text "Keepout" at 107.081,67.371 h1.2 r90
  text "Keepout" at 108.605,34.478 h1.2 r90
  text "Keepout" at 1.259,26.906 h1.2 r90
  text "+24В - 2 конт." at 0.5,-44.586 h2
  text "SPI - 5 конт /  / USB-4 конт / OVERCUR - 1 конт" at 44.5,-45.586 h2
  text "VDD_3V3 - 1 конт min / VDD_5V0 - 1 конт min / DGND - 1 конт min" at 20,-46.086 h2
  text "3 контакта на UART: / UART_RX\TX / RESERN_IN_BUF" at 38.5,-67.086 h2
  text "Предположительное число сигналов: / DI1...DI10 - 10 сигналов / RS485 - 4 контакта / DO1...DO12 - 12 конт / ---- / 26 конт" at -1.5,-72.586 h2
Top assy:
  lines w0: 0,17.396 109.2,17.396 ; 0,19.05 109.2,19.05
Bottom assy:
  circle w0.2: c1.4,58.05 r0.003
  lines w0.2: 0.2,46.85 ccw(c0.2,48.05) 1.4,48.05 1.4,58.05 2.5,58.05 106.7,58.05 107.8,58.05 107.8,48.05 ccw(c109,48.05) 109,46.85 109.2,46.85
